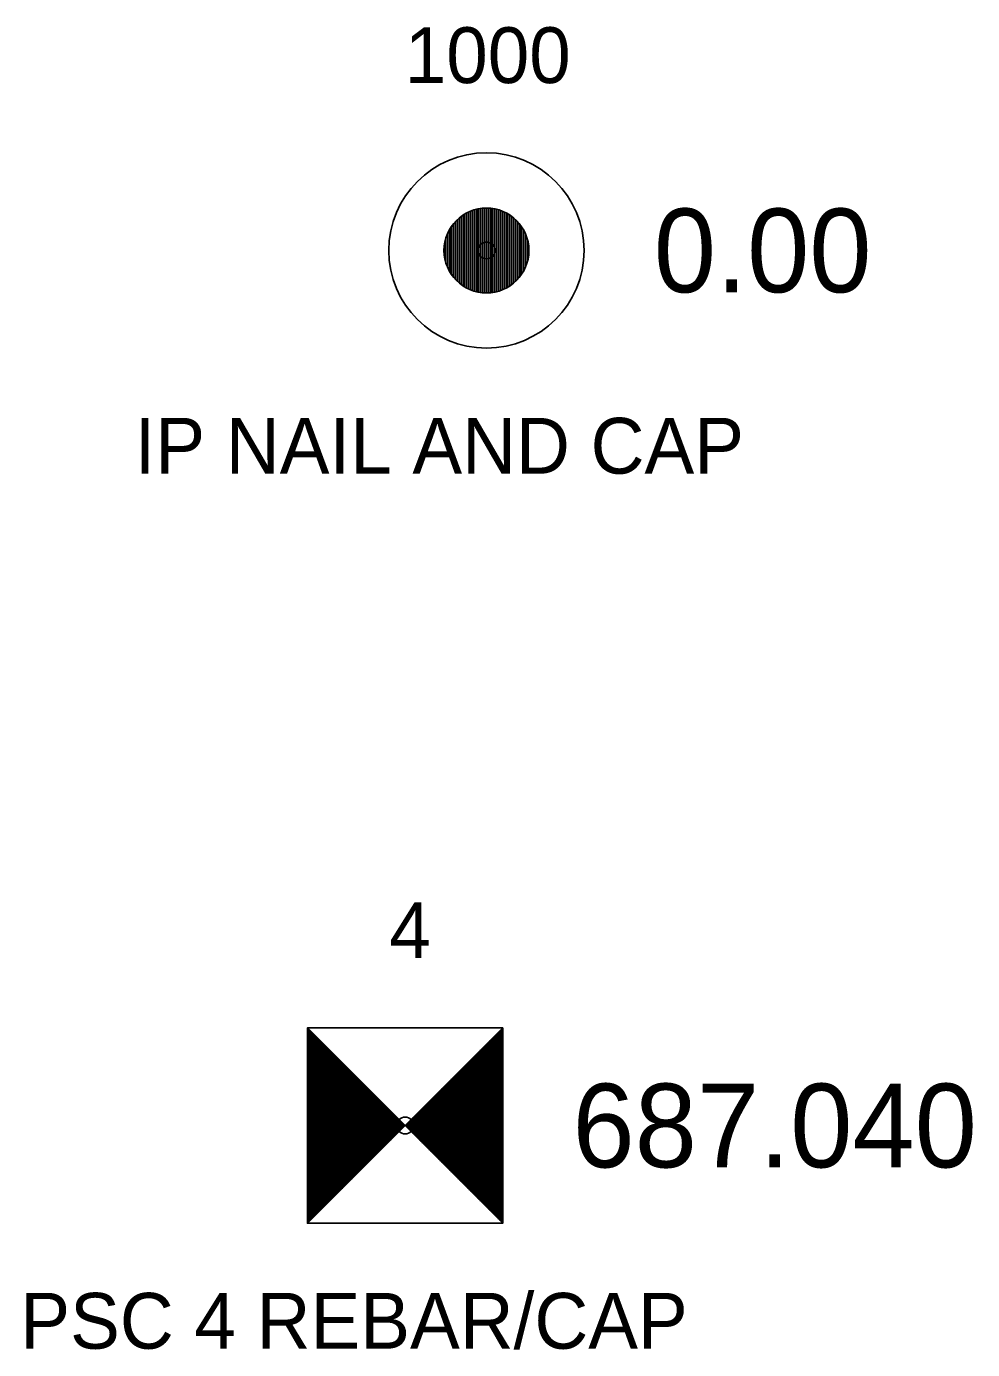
# Model space of a CAD drawing. Extents: x 1655137 to 1657928, y 1003994 to 1005407.
# Drawn here: x 1657473.46 to 1657490.42, y 1004400.25 to 1004423.96 of the extents above; entities that cross this region are included whole.
import ezdxf

# ---------------------------------------------------------------- set-up
doc = ezdxf.new("R2010")
doc.units = 0
for name, color, linetype in [('RD_EX_DV_Prop_txCode', 7, 'Continuous'), ('RD_EX_DV_PropPin', 7, 'Continuous'), ('RD_EX_TX_DV_Prop_ELEV', 7, 'Continuous'), ('RD_HC_Survey', 7, 'Continuous'), ('RD_HC_Survey_ELEV', 7, 'Continuous'), ('RD_HC_txCode', 7, 'Continuous'), ('RD_SMD_Locator', 7, 'Continuous')]:
    doc.layers.add(name, color=color, linetype=linetype)

msp = doc.modelspace()

# ---------------------------------------------------------------- linework, layer by layer
at = {"layer": 'RD_EX_DV_PropPin'}
for p, q in [((1657481.181, 1004419.397), (1657481.181, 1004420.498)), ((1657481.216, 1004419.366), (1657481.216, 1004420.53)), ((1657481.251, 1004419.338), (1657481.251, 1004420.558)), ((1657481.286, 1004419.313), (1657481.286, 1004420.582)), ((1657481.321, 1004419.291), (1657481.321, 1004420.604)), ((1657481.356, 1004419.272), (1657481.356, 1004420.623)), ((1657481.391, 1004419.255), (1657481.391, 1004420.64)), ((1657481.426, 1004419.24), (1657481.426, 1004420.655)), ((1657481.461, 1004419.227), (1657481.461, 1004420.668)), ((1657481.496, 1004419.216), (1657481.496, 1004420.679)), ((1657481.531, 1004419.207), (1657481.531, 1004420.688)), ((1657481.566, 1004419.2), (1657481.566, 1004420.696)), ((1657481.601, 1004419.194), (1657481.601, 1004420.701)), ((1657481.636, 1004419.19), (1657481.636, 1004420.705)), ((1657481.671, 1004419.187), (1657481.671, 1004420.708)), ((1657481.706, 1004419.187), (1657481.706, 1004420.709)), ((1657481.741, 1004419.187), (1657481.741, 1004420.708)), ((1657481.776, 1004419.19), (1657481.776, 1004420.705)), ((1657481.811, 1004419.194), (1657481.811, 1004420.701)), ((1657481.846, 1004419.2), (1657481.846, 1004420.696)), ((1657481.881, 1004419.207), (1657481.881, 1004420.688)), ((1657481.916, 1004419.216), (1657481.916, 1004420.679)), ((1657481.951, 1004419.227), (1657481.951, 1004420.668)), ((1657481.986, 1004419.24), (1657481.986, 1004420.655)), ((1657482.022, 1004419.255), (1657482.022, 1004420.64)), ((1657482.057, 1004419.272), (1657482.057, 1004420.623)), ((1657482.092, 1004419.291), (1657482.092, 1004420.604)), ((1657482.127, 1004419.313), (1657482.127, 1004420.582)), ((1657482.162, 1004419.338), (1657482.162, 1004420.558)), ((1657482.197, 1004419.366), (1657482.197, 1004420.53)), ((1657482.232, 1004419.397), (1657482.232, 1004420.498)), ((1657481.041, 1004419.578), (1657481.041, 1004420.317)), ((1657481.076, 1004419.521), (1657481.076, 1004420.374)), ((1657481.111, 1004419.474), (1657481.111, 1004420.422)), ((1657481.146, 1004419.433), (1657481.146, 1004420.463)), ((1657482.267, 1004419.433), (1657482.267, 1004420.463)), ((1657482.302, 1004419.474), (1657482.302, 1004420.422)), ((1657482.337, 1004419.521), (1657482.337, 1004420.374)), ((1657482.372, 1004419.578), (1657482.372, 1004420.317)), ((1657480.971, 1004419.752), (1657480.971, 1004420.144)), ((1657481.006, 1004419.65), (1657481.006, 1004420.246)), ((1657482.407, 1004419.65), (1657482.407, 1004420.246)), ((1657482.442, 1004419.752), (1657482.442, 1004420.144))]:
    msp.add_line(p, q, dxfattribs=at)
for radius in [1.75, 0.761]:
    msp.add_circle((1657481.706, 1004419.948), radius, dxfattribs=at)
at = {"layer": 'RD_HC_Survey'}
for p, q in [((1657478.498, 1004406.014), (1657481.998, 1004402.515)), ((1657481.998, 1004406.014), (1657478.498, 1004402.515)), ((1657478.523, 1004405.99), (1657478.523, 1004402.539)), ((1657478.547, 1004405.965), (1657478.547, 1004402.564)), ((1657478.572, 1004405.94), (1657478.572, 1004402.589)), ((1657478.597, 1004405.915), (1657478.597, 1004402.614)), ((1657478.622, 1004405.891), (1657478.622, 1004402.638)), ((1657478.646, 1004405.866), (1657478.646, 1004402.663)), ((1657478.671, 1004405.841), (1657478.671, 1004402.688)), ((1657478.696, 1004405.817), (1657478.696, 1004402.712)), ((1657478.721, 1004405.792), (1657478.721, 1004402.737)), ((1657481.775, 1004405.792), (1657481.775, 1004402.737)), ((1657481.8, 1004405.817), (1657481.8, 1004402.712)), ((1657481.825, 1004405.841), (1657481.825, 1004402.688)), ((1657481.849, 1004405.866), (1657481.849, 1004402.663)), ((1657481.874, 1004405.891), (1657481.874, 1004402.638)), ((1657481.899, 1004405.915), (1657481.899, 1004402.614)), ((1657481.924, 1004405.94), (1657481.924, 1004402.589)), ((1657481.948, 1004405.965), (1657481.948, 1004402.564)), ((1657481.973, 1004405.99), (1657481.973, 1004402.539)), ((1657478.745, 1004405.767), (1657478.745, 1004402.762)), ((1657478.77, 1004405.742), (1657478.77, 1004402.787)), ((1657478.795, 1004405.718), (1657478.795, 1004402.811)), ((1657478.82, 1004405.693), (1657478.82, 1004402.836)), ((1657478.844, 1004405.668), (1657478.844, 1004402.861)), ((1657478.869, 1004405.643), (1657478.869, 1004402.886)), ((1657478.894, 1004405.619), (1657478.894, 1004402.91)), ((1657478.919, 1004405.594), (1657478.919, 1004402.935)), ((1657478.943, 1004405.569), (1657478.943, 1004402.96)), ((1657481.552, 1004405.569), (1657481.552, 1004402.96)), ((1657481.577, 1004405.594), (1657481.577, 1004402.935)), ((1657481.602, 1004405.619), (1657481.602, 1004402.91)), ((1657481.627, 1004405.643), (1657481.627, 1004402.886)), ((1657481.651, 1004405.668), (1657481.651, 1004402.861)), ((1657481.676, 1004405.693), (1657481.676, 1004402.836)), ((1657481.701, 1004405.718), (1657481.701, 1004402.811)), ((1657481.726, 1004405.742), (1657481.726, 1004402.787)), ((1657481.75, 1004405.767), (1657481.75, 1004402.762)), ((1657478.968, 1004405.544), (1657478.968, 1004402.985)), ((1657478.993, 1004405.52), (1657478.993, 1004403.009)), ((1657479.018, 1004405.495), (1657479.018, 1004403.034)), ((1657479.042, 1004405.47), (1657479.042, 1004403.059)), ((1657479.067, 1004405.445), (1657479.067, 1004403.084)), ((1657479.092, 1004405.421), (1657479.092, 1004403.108)), ((1657479.117, 1004405.396), (1657479.117, 1004403.133)), ((1657479.141, 1004405.371), (1657479.141, 1004403.158)), ((1657479.166, 1004405.346), (1657479.166, 1004403.183)), ((1657479.191, 1004405.322), (1657479.191, 1004403.207)), ((1657481.305, 1004405.322), (1657481.305, 1004403.207)), ((1657481.33, 1004405.346), (1657481.33, 1004403.183)), ((1657481.354, 1004405.371), (1657481.354, 1004403.158)), ((1657481.379, 1004405.396), (1657481.379, 1004403.133)), ((1657481.404, 1004405.421), (1657481.404, 1004403.108)), ((1657481.429, 1004405.445), (1657481.429, 1004403.084)), ((1657481.453, 1004405.47), (1657481.453, 1004403.059)), ((1657481.478, 1004405.495), (1657481.478, 1004403.034)), ((1657481.503, 1004405.52), (1657481.503, 1004403.009)), ((1657481.528, 1004405.544), (1657481.528, 1004402.985)), ((1657479.216, 1004405.297), (1657479.216, 1004403.232)), ((1657479.24, 1004405.272), (1657479.24, 1004403.257)), ((1657479.265, 1004405.247), (1657479.265, 1004403.282)), ((1657479.29, 1004405.223), (1657479.29, 1004403.306)), ((1657479.315, 1004405.198), (1657479.315, 1004403.331)), ((1657479.339, 1004405.173), (1657479.339, 1004403.356)), ((1657479.364, 1004405.148), (1657479.364, 1004403.381)), ((1657479.389, 1004405.124), (1657479.389, 1004403.405)), ((1657479.414, 1004405.099), (1657479.414, 1004403.43)), ((1657479.438, 1004405.074), (1657479.438, 1004403.455)), ((1657481.057, 1004405.074), (1657481.057, 1004403.455)), ((1657481.082, 1004405.099), (1657481.082, 1004403.43)), ((1657481.107, 1004405.124), (1657481.107, 1004403.405)), ((1657481.132, 1004405.148), (1657481.132, 1004403.381)), ((1657481.156, 1004405.173), (1657481.156, 1004403.356)), ((1657481.181, 1004405.198), (1657481.181, 1004403.331)), ((1657481.206, 1004405.223), (1657481.206, 1004403.306)), ((1657481.231, 1004405.247), (1657481.231, 1004403.282)), ((1657481.255, 1004405.272), (1657481.255, 1004403.257)), ((1657481.28, 1004405.297), (1657481.28, 1004403.232)), ((1657479.463, 1004405.049), (1657479.463, 1004403.48)), ((1657479.488, 1004405.025), (1657479.488, 1004403.504)), ((1657479.513, 1004405), (1657479.513, 1004403.529)), ((1657479.537, 1004404.975), (1657479.537, 1004403.554)), ((1657479.562, 1004404.95), (1657479.562, 1004403.579)), ((1657479.587, 1004404.926), (1657479.587, 1004403.603)), ((1657479.611, 1004404.901), (1657479.611, 1004403.628)), ((1657479.636, 1004404.876), (1657479.636, 1004403.653)), ((1657479.661, 1004404.851), (1657479.661, 1004403.678)), ((1657480.835, 1004404.851), (1657480.835, 1004403.678)), ((1657480.859, 1004404.876), (1657480.859, 1004403.653)), ((1657480.884, 1004404.901), (1657480.884, 1004403.628)), ((1657480.909, 1004404.926), (1657480.909, 1004403.603)), ((1657480.934, 1004404.95), (1657480.934, 1004403.579)), ((1657480.958, 1004404.975), (1657480.958, 1004403.554)), ((1657480.983, 1004405), (1657480.983, 1004403.529)), ((1657481.008, 1004405.025), (1657481.008, 1004403.504)), ((1657481.033, 1004405.049), (1657481.033, 1004403.48)), ((1657479.686, 1004404.827), (1657479.686, 1004403.702)), ((1657479.71, 1004404.802), (1657479.71, 1004403.727)), ((1657479.735, 1004404.777), (1657479.735, 1004403.752)), ((1657479.76, 1004404.752), (1657479.76, 1004403.777)), ((1657479.785, 1004404.728), (1657479.785, 1004403.801)), ((1657479.809, 1004404.703), (1657479.809, 1004403.826)), ((1657479.834, 1004404.678), (1657479.834, 1004403.851)), ((1657479.859, 1004404.653), (1657479.859, 1004403.876)), ((1657479.884, 1004404.629), (1657479.884, 1004403.9)), ((1657479.908, 1004404.604), (1657479.908, 1004403.925)), ((1657480.587, 1004404.604), (1657480.587, 1004403.925)), ((1657480.612, 1004404.629), (1657480.612, 1004403.9)), ((1657480.637, 1004404.653), (1657480.637, 1004403.876)), ((1657480.661, 1004404.678), (1657480.661, 1004403.851)), ((1657480.686, 1004404.703), (1657480.686, 1004403.826)), ((1657480.711, 1004404.728), (1657480.711, 1004403.801)), ((1657480.736, 1004404.752), (1657480.736, 1004403.777)), ((1657480.76, 1004404.777), (1657480.76, 1004403.752)), ((1657480.785, 1004404.802), (1657480.785, 1004403.727)), ((1657480.81, 1004404.827), (1657480.81, 1004403.702)), ((1657479.933, 1004404.579), (1657479.933, 1004403.95)), ((1657479.958, 1004404.554), (1657479.958, 1004403.975)), ((1657479.983, 1004404.53), (1657479.983, 1004403.999)), ((1657480.007, 1004404.505), (1657480.007, 1004404.024)), ((1657480.032, 1004404.48), (1657480.032, 1004404.049)), ((1657480.057, 1004404.455), (1657480.057, 1004404.074)), ((1657480.082, 1004404.431), (1657480.082, 1004404.098)), ((1657480.106, 1004404.406), (1657480.106, 1004404.123)), ((1657480.131, 1004404.381), (1657480.131, 1004404.148)), ((1657480.364, 1004404.381), (1657480.364, 1004404.148)), ((1657480.389, 1004404.406), (1657480.389, 1004404.123)), ((1657480.414, 1004404.431), (1657480.414, 1004404.098)), ((1657480.439, 1004404.455), (1657480.439, 1004404.074)), ((1657480.463, 1004404.48), (1657480.463, 1004404.049)), ((1657480.488, 1004404.505), (1657480.488, 1004404.024)), ((1657480.513, 1004404.53), (1657480.513, 1004403.999)), ((1657480.538, 1004404.554), (1657480.538, 1004403.975)), ((1657480.562, 1004404.579), (1657480.562, 1004403.95)), ((1657480.156, 1004404.356), (1657480.156, 1004404.173)), ((1657480.181, 1004404.332), (1657480.181, 1004404.197)), ((1657480.205, 1004404.307), (1657480.205, 1004404.222)), ((1657480.23, 1004404.282), (1657480.23, 1004404.247)), ((1657480.265, 1004404.282), (1657480.265, 1004404.247)), ((1657480.29, 1004404.307), (1657480.29, 1004404.222)), ((1657480.315, 1004404.332), (1657480.315, 1004404.197)), ((1657480.34, 1004404.356), (1657480.34, 1004404.173))]:
    msp.add_line(p, q, dxfattribs=at)
msp.add_lwpolyline([(1657481.998, 1004406.014), (1657478.498, 1004406.014), (1657478.498, 1004402.515), (1657481.998, 1004402.515)], close=True, dxfattribs=at)
at = {"layer": 'RD_SMD_Locator'}
for centre in [(1657481.706, 1004419.948), (1657480.248, 1004404.265)]:
    msp.add_circle(centre, 0.15, dxfattribs=at)

# ---------------------------------------------------------------- texts
at = {"layer": 'RD_EX_DV_Prop_txCode'}
for s, p in [('1000', (1657480.242, 1004422.948)), ('IP NAIL AND CAP', (1657475.399, 1004415.948))]:
    msp.add_text(s, height=1, dxfattribs=at).set_placement(p)
at = {"layer": 'RD_EX_TX_DV_Prop_ELEV'}
msp.add_text('0.00', height=1.5, dxfattribs=at).set_placement((1657484.706, 1004419.198))
at = {"layer": 'RD_HC_Survey_ELEV'}
msp.add_text('687.040', height=1.5, dxfattribs=at).set_placement((1657483.248, 1004403.515))
at = {"layer": 'RD_HC_txCode'}
for s, p in [('4', (1657479.964, 1004407.265)), ('PSC 4 REBAR/CAP', (1657473.35, 1004400.265))]:
    msp.add_text(s, height=1, dxfattribs=at).set_placement(p)

doc.saveas('drawing.dxf')
